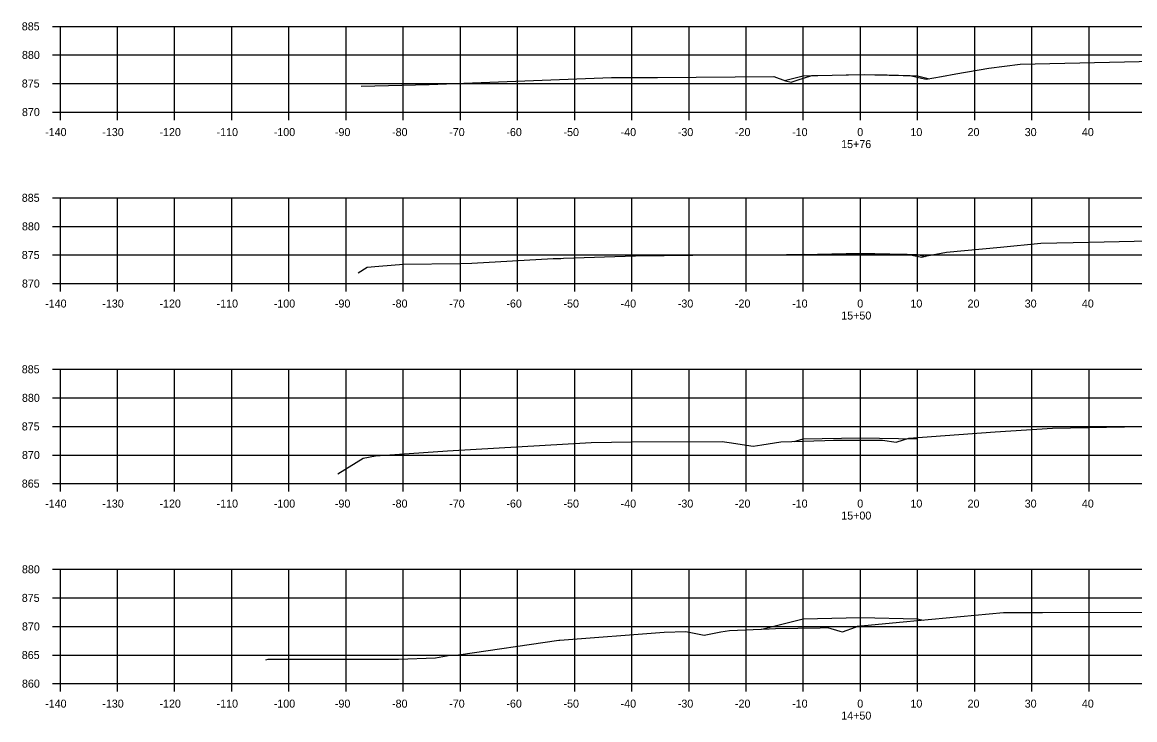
# Model space of a CAD drawing. Extents: x 1098669 to 1198896, y 698679 to 704410.
# Drawn here: x 1110634.5 to 1110829.2, y 701942.8 to 702064.8 of the extents above; entities that cross this region are included whole.
import ezdxf

# ---------------------------------------------------------------- set-up
doc = ezdxf.new("R2010")
doc.units = 0
for name, color, linetype in [('Proposed Surface', 7, 'Continuous'), ('R_Axis', 7, 'Continuous'), ('R_Axis Annot', 7, 'Continuous'), ('R_Fin Surface', 7, 'Continuous'), ('R_Grid', 7, 'Continuous')]:
    doc.layers.add(name, color=color, linetype=linetype)

msp = doc.modelspace()

# ---------------------------------------------------------------- linework, layer by layer
at = {"layer": 'Proposed Surface'}
for points in [[(1110693.81, 702053.64), (1110705.71, 702053.98), (1110737.59, 702055.16), (1110745.67, 702055.2), (1110766.01, 702055.35), (1110768.06, 702054.62), (1110769.01, 702054.38), (1110770.07, 702054.71), (1110772.65, 702055.53), (1110776.23, 702055.61), (1110781.94, 702055.71), (1110785.84, 702055.63), (1110789.87, 702055.55), (1110791.3, 702055.19), (1110792.68, 702054.87), (1110795.35, 702055.35), (1110797.85, 702055.84), (1110803.61, 702056.79), (1110809.13, 702057.49), (1110832.57, 702058.01)], [(1110693.25, 702021), (1110694.85, 702021.97), (1110696.91, 702022.15), (1110701.23, 702022.52), (1110711.07, 702022.64), (1110713.18, 702022.72), (1110727.38, 702023.5), (1110728.73, 702023.52), (1110729.17, 702023.55), (1110741.79, 702023.95), (1110751.8, 702024.08), (1110757.18, 702024.13), (1110765.02, 702024.17), (1110771.44, 702024.25), (1110772.09, 702024.24), (1110777.76, 702024.33), (1110781.26, 702024.39), (1110783.25, 702024.36), (1110789.31, 702024.28), (1110791.3, 702023.88), (1110791.9, 702023.77), (1110792.76, 702023.95), (1110796.24, 702024.62), (1110805.66, 702025.49), (1110812.7, 702026.2), (1110821.16, 702026.39), (1110849.97, 702027)], [(1110689.73, 701985.84), (1110694.15, 701988.56), (1110696.3, 701989.01), (1110708.92, 701989.85), (1110734.04, 701991.33), (1110741.15, 701991.42), (1110756.96, 701991.48), (1110758.17, 701991.31), (1110762.38, 701990.69), (1110763.88, 701990.93), (1110767.25, 701991.46), (1110774.91, 701991.67), (1110776.44, 701991.71), (1110777.03, 701991.72), (1110782.87, 701991.74), (1110784.96, 701991.75), (1110785.02, 701991.75), (1110787.4, 701991.37), (1110787.57, 701991.42), (1110789.64, 701992.1), (1110804.7, 701993.2), (1110814.79, 701993.81), (1110830.49, 701994.13)], [(1110677.13, 701953.27), (1110677.55, 701953.41), (1110700.33, 701953.42), (1110706.83, 701953.64), (1110709.36, 701954.08), (1110710.8, 701954.18), (1110728.38, 701956.71), (1110728.54, 701956.73), (1110746.83, 701958.16), (1110750.59, 701958.25), (1110752.95, 701957.77), (1110753.83, 701957.61), (1110756.75, 701958.17), (1110758.27, 701958.42), (1110765.17, 701958.73), (1110766.29, 701958.79), (1110774.11, 701958.91), (1110775.37, 701958.93), (1110777.54, 701958.31), (1110778.03, 701958.18), (1110780.32, 701959.03), (1110780.65, 701959.17), (1110788.65, 701959.92), (1110806.16, 701961.59), (1110812.99, 701961.56), (1110839.28, 701961.64)]]:
    msp.add_lwpolyline(points, dxfattribs=at)
at = {"layer": 'R_Axis'}
for p, q in [((1110639.76, 702064.13), (1110641.16, 702064.13)), ((1110641.16, 702049.13), (1110641.16, 702064.13)), ((1110639.76, 702059.13), (1110641.16, 702059.13)), ((1110639.76, 702054.13), (1110641.16, 702054.13)), ((1110639.76, 702049.13), (1110641.16, 702049.13)), ((1110641.16, 702049.13), (1110921.16, 702049.13)), ((1110641.16, 702047.73), (1110641.16, 702049.13)), ((1110651.16, 702047.73), (1110651.16, 702049.13)), ((1110661.16, 702047.73), (1110661.16, 702049.13)), ((1110671.16, 702047.73), (1110671.16, 702049.13)), ((1110681.16, 702047.73), (1110681.16, 702049.13)), ((1110691.16, 702047.73), (1110691.16, 702049.13)), ((1110701.16, 702047.73), (1110701.16, 702049.13)), ((1110711.16, 702047.73), (1110711.16, 702049.13)), ((1110721.16, 702047.73), (1110721.16, 702049.13)), ((1110731.16, 702047.73), (1110731.16, 702049.13)), ((1110741.16, 702047.73), (1110741.16, 702049.13)), ((1110751.16, 702047.73), (1110751.16, 702049.13)), ((1110761.16, 702047.73), (1110761.16, 702049.13)), ((1110771.16, 702047.73), (1110771.16, 702049.13)), ((1110781.16, 702047.73), (1110781.16, 702049.13)), ((1110791.16, 702047.73), (1110791.16, 702049.13)), ((1110801.16, 702047.73), (1110801.16, 702049.13)), ((1110811.16, 702047.73), (1110811.16, 702049.13)), ((1110821.16, 702047.73), (1110821.16, 702049.13)), ((1110639.76, 702034.13), (1110641.16, 702034.13)), ((1110641.16, 702019.13), (1110641.16, 702034.13)), ((1110639.76, 702029.13), (1110641.16, 702029.13)), ((1110639.76, 702024.13), (1110641.16, 702024.13)), ((1110639.76, 702019.13), (1110641.16, 702019.13)), ((1110641.16, 702019.13), (1110921.16, 702019.13)), ((1110641.16, 702017.73), (1110641.16, 702019.13)), ((1110651.16, 702017.73), (1110651.16, 702019.13)), ((1110661.16, 702017.73), (1110661.16, 702019.13)), ((1110671.16, 702017.73), (1110671.16, 702019.13)), ((1110681.16, 702017.73), (1110681.16, 702019.13)), ((1110691.16, 702017.73), (1110691.16, 702019.13)), ((1110701.16, 702017.73), (1110701.16, 702019.13)), ((1110711.16, 702017.73), (1110711.16, 702019.13)), ((1110721.16, 702017.73), (1110721.16, 702019.13)), ((1110731.16, 702017.73), (1110731.16, 702019.13)), ((1110741.16, 702017.73), (1110741.16, 702019.13)), ((1110751.16, 702017.73), (1110751.16, 702019.13)), ((1110761.16, 702017.73), (1110761.16, 702019.13)), ((1110771.16, 702017.73), (1110771.16, 702019.13)), ((1110781.16, 702017.73), (1110781.16, 702019.13)), ((1110791.16, 702017.73), (1110791.16, 702019.13)), ((1110801.16, 702017.73), (1110801.16, 702019.13)), ((1110811.16, 702017.73), (1110811.16, 702019.13)), ((1110821.16, 702017.73), (1110821.16, 702019.13)), ((1110639.76, 702004.13), (1110641.16, 702004.13)), ((1110641.16, 701984.13), (1110641.16, 702004.13)), ((1110639.76, 701999.13), (1110641.16, 701999.13)), ((1110639.76, 701994.13), (1110641.16, 701994.13)), ((1110639.76, 701989.13), (1110641.16, 701989.13)), ((1110639.76, 701984.13), (1110641.16, 701984.13)), ((1110641.16, 701984.13), (1110921.16, 701984.13)), ((1110641.16, 701982.73), (1110641.16, 701984.13)), ((1110651.16, 701982.73), (1110651.16, 701984.13)), ((1110661.16, 701982.73), (1110661.16, 701984.13)), ((1110671.16, 701982.73), (1110671.16, 701984.13)), ((1110681.16, 701982.73), (1110681.16, 701984.13)), ((1110691.16, 701982.73), (1110691.16, 701984.13)), ((1110701.16, 701982.73), (1110701.16, 701984.13)), ((1110711.16, 701982.73), (1110711.16, 701984.13)), ((1110721.16, 701982.73), (1110721.16, 701984.13)), ((1110731.16, 701982.73), (1110731.16, 701984.13)), ((1110741.16, 701982.73), (1110741.16, 701984.13)), ((1110751.16, 701982.73), (1110751.16, 701984.13)), ((1110761.16, 701982.73), (1110761.16, 701984.13)), ((1110771.16, 701982.73), (1110771.16, 701984.13)), ((1110781.16, 701982.73), (1110781.16, 701984.13)), ((1110791.16, 701982.73), (1110791.16, 701984.13)), ((1110801.16, 701982.73), (1110801.16, 701984.13)), ((1110811.16, 701982.73), (1110811.16, 701984.13)), ((1110821.16, 701982.73), (1110821.16, 701984.13)), ((1110639.76, 701969.13), (1110641.16, 701969.13)), ((1110641.16, 701949.13), (1110641.16, 701969.13)), ((1110639.76, 701964.13), (1110641.16, 701964.13)), ((1110639.76, 701959.13), (1110641.16, 701959.13)), ((1110639.76, 701954.13), (1110641.16, 701954.13)), ((1110639.76, 701949.13), (1110641.16, 701949.13)), ((1110641.16, 701949.13), (1110921.16, 701949.13)), ((1110641.16, 701947.73), (1110641.16, 701949.13)), ((1110651.16, 701947.73), (1110651.16, 701949.13)), ((1110661.16, 701947.73), (1110661.16, 701949.13)), ((1110671.16, 701947.73), (1110671.16, 701949.13)), ((1110681.16, 701947.73), (1110681.16, 701949.13)), ((1110691.16, 701947.73), (1110691.16, 701949.13)), ((1110701.16, 701947.73), (1110701.16, 701949.13)), ((1110711.16, 701947.73), (1110711.16, 701949.13)), ((1110721.16, 701947.73), (1110721.16, 701949.13)), ((1110731.16, 701947.73), (1110731.16, 701949.13)), ((1110741.16, 701947.73), (1110741.16, 701949.13)), ((1110751.16, 701947.73), (1110751.16, 701949.13)), ((1110761.16, 701947.73), (1110761.16, 701949.13)), ((1110771.16, 701947.73), (1110771.16, 701949.13)), ((1110781.16, 701947.73), (1110781.16, 701949.13)), ((1110791.16, 701947.73), (1110791.16, 701949.13)), ((1110801.16, 701947.73), (1110801.16, 701949.13)), ((1110811.16, 701947.73), (1110811.16, 701949.13)), ((1110821.16, 701947.73), (1110821.16, 701949.13))]:
    msp.add_line(p, q, dxfattribs=at)
at = {"layer": 'R_Fin Surface'}
for points in [[(1110767.89, 702054.68), (1110767.89, 702054.68), (1110771.16, 702055.49), (1110771.17, 702055.49), (1110781.16, 702055.69), (1110791.15, 702055.49), (1110791.16, 702055.49), (1110791.16, 702055.49), (1110793.24, 702054.97)], [(1110771.16, 702024.22), (1110781.16, 702024.42), (1110791.16, 702024.22), (1110792.48, 702023.89)], [(1110769.55, 701991.52), (1110771.16, 701991.93), (1110781.16, 701992.13), (1110791.16, 701991.93)], [(1110763.9, 701958.67), (1110771.16, 701960.49), (1110781.16, 701960.69), (1110791.16, 701960.49), (1110792.11, 701960.25)]]:
    msp.add_lwpolyline(points, dxfattribs=at)
at = {"layer": 'R_Grid'}
for p, q in [((1110641.16, 702064.13), (1110921.16, 702064.13)), ((1110641.16, 702049.13), (1110641.16, 702064.13)), ((1110651.16, 702049.13), (1110651.16, 702064.13)), ((1110661.16, 702049.13), (1110661.16, 702064.13)), ((1110671.16, 702049.13), (1110671.16, 702064.13)), ((1110681.16, 702049.13), (1110681.16, 702064.13)), ((1110691.16, 702049.13), (1110691.16, 702064.13)), ((1110701.16, 702049.13), (1110701.16, 702064.13)), ((1110711.16, 702049.13), (1110711.16, 702064.13)), ((1110721.16, 702049.13), (1110721.16, 702064.13)), ((1110731.16, 702049.13), (1110731.16, 702064.13)), ((1110741.16, 702049.13), (1110741.16, 702064.13)), ((1110751.16, 702049.13), (1110751.16, 702064.13)), ((1110761.16, 702049.13), (1110761.16, 702064.13)), ((1110771.16, 702049.13), (1110771.16, 702064.13)), ((1110781.16, 702049.13), (1110781.16, 702064.13)), ((1110791.16, 702049.13), (1110791.16, 702064.13)), ((1110801.16, 702049.13), (1110801.16, 702064.13)), ((1110811.16, 702049.13), (1110811.16, 702064.13)), ((1110821.16, 702049.13), (1110821.16, 702064.13)), ((1110641.16, 702059.13), (1110921.16, 702059.13)), ((1110641.16, 702054.13), (1110921.16, 702054.13)), ((1110641.16, 702049.13), (1110921.16, 702049.13)), ((1110641.16, 702034.13), (1110921.16, 702034.13)), ((1110641.16, 702019.13), (1110641.16, 702034.13)), ((1110651.16, 702019.13), (1110651.16, 702034.13)), ((1110661.16, 702019.13), (1110661.16, 702034.13)), ((1110671.16, 702019.13), (1110671.16, 702034.13)), ((1110681.16, 702019.13), (1110681.16, 702034.13)), ((1110691.16, 702019.13), (1110691.16, 702034.13)), ((1110701.16, 702019.13), (1110701.16, 702034.13)), ((1110711.16, 702019.13), (1110711.16, 702034.13)), ((1110721.16, 702019.13), (1110721.16, 702034.13)), ((1110731.16, 702019.13), (1110731.16, 702034.13)), ((1110741.16, 702019.13), (1110741.16, 702034.13)), ((1110751.16, 702019.13), (1110751.16, 702034.13)), ((1110761.16, 702019.13), (1110761.16, 702034.13)), ((1110771.16, 702019.13), (1110771.16, 702034.13)), ((1110781.16, 702019.13), (1110781.16, 702034.13)), ((1110791.16, 702019.13), (1110791.16, 702034.13)), ((1110801.16, 702019.13), (1110801.16, 702034.13)), ((1110811.16, 702019.13), (1110811.16, 702034.13)), ((1110821.16, 702019.13), (1110821.16, 702034.13)), ((1110641.16, 702029.13), (1110921.16, 702029.13)), ((1110641.16, 702024.13), (1110921.16, 702024.13)), ((1110641.16, 702019.13), (1110921.16, 702019.13)), ((1110641.16, 702004.13), (1110921.16, 702004.13)), ((1110641.16, 701984.13), (1110641.16, 702004.13)), ((1110651.16, 701984.13), (1110651.16, 702004.13)), ((1110661.16, 701984.13), (1110661.16, 702004.13)), ((1110671.16, 701984.13), (1110671.16, 702004.13)), ((1110681.16, 701984.13), (1110681.16, 702004.13)), ((1110691.16, 701984.13), (1110691.16, 702004.13)), ((1110701.16, 701984.13), (1110701.16, 702004.13)), ((1110711.16, 701984.13), (1110711.16, 702004.13)), ((1110721.16, 701984.13), (1110721.16, 702004.13)), ((1110731.16, 701984.13), (1110731.16, 702004.13)), ((1110741.16, 701984.13), (1110741.16, 702004.13)), ((1110751.16, 701984.13), (1110751.16, 702004.13)), ((1110761.16, 701984.13), (1110761.16, 702004.13)), ((1110771.16, 701984.13), (1110771.16, 702004.13)), ((1110781.16, 701984.13), (1110781.16, 702004.13)), ((1110791.16, 701984.13), (1110791.16, 702004.13)), ((1110801.16, 701984.13), (1110801.16, 702004.13)), ((1110811.16, 701984.13), (1110811.16, 702004.13)), ((1110821.16, 701984.13), (1110821.16, 702004.13)), ((1110641.16, 701999.13), (1110921.16, 701999.13)), ((1110641.16, 701994.13), (1110921.16, 701994.13)), ((1110641.16, 701989.13), (1110921.16, 701989.13)), ((1110641.16, 701984.13), (1110921.16, 701984.13)), ((1110641.16, 701969.13), (1110921.16, 701969.13)), ((1110641.16, 701949.13), (1110641.16, 701969.13)), ((1110651.16, 701949.13), (1110651.16, 701969.13)), ((1110661.16, 701949.13), (1110661.16, 701969.13)), ((1110671.16, 701949.13), (1110671.16, 701969.13)), ((1110681.16, 701949.13), (1110681.16, 701969.13)), ((1110691.16, 701949.13), (1110691.16, 701969.13)), ((1110701.16, 701949.13), (1110701.16, 701969.13)), ((1110711.16, 701949.13), (1110711.16, 701969.13)), ((1110721.16, 701949.13), (1110721.16, 701969.13)), ((1110731.16, 701949.13), (1110731.16, 701969.13)), ((1110741.16, 701949.13), (1110741.16, 701969.13)), ((1110751.16, 701949.13), (1110751.16, 701969.13)), ((1110761.16, 701949.13), (1110761.16, 701969.13)), ((1110771.16, 701949.13), (1110771.16, 701969.13)), ((1110781.16, 701949.13), (1110781.16, 701969.13)), ((1110791.16, 701949.13), (1110791.16, 701969.13)), ((1110801.16, 701949.13), (1110801.16, 701969.13)), ((1110811.16, 701949.13), (1110811.16, 701969.13)), ((1110821.16, 701949.13), (1110821.16, 701969.13)), ((1110641.16, 701964.13), (1110921.16, 701964.13)), ((1110641.16, 701959.13), (1110921.16, 701959.13)), ((1110641.16, 701954.13), (1110921.16, 701954.13)), ((1110641.16, 701949.13), (1110921.16, 701949.13))]:
    msp.add_line(p, q, dxfattribs=at)

# ---------------------------------------------------------------- texts
at = {"layer": 'R_Axis Annot'}
for s, p in [('885', (1110634.41, 702063.43)), ('880', (1110634.44, 702058.43)), ('875', (1110634.41, 702053.43)), ('870', (1110634.44, 702048.43)), ('-140', (1110638.5, 702044.93)), ('-130', (1110648.5, 702044.93)), ('-120', (1110658.5, 702044.93)), ('-110', (1110668.5, 702044.93)), ('-100', (1110678.5, 702044.93)), ('-90', (1110689.2, 702044.93)), ('-80', (1110699.2, 702044.93)), ('-70', (1110709.2, 702044.93)), ('-60', (1110719.2, 702044.93)), ('-50', (1110729.2, 702044.93)), ('-40', (1110739.2, 702044.93)), ('-30', (1110749.2, 702044.93)), ('-20', (1110759.2, 702044.93)), ('-10', (1110769.2, 702044.93)), ('0', (1110780.6, 702044.93)), ('10', (1110789.9, 702044.93)), ('20', (1110799.9, 702044.93)), ('30', (1110809.9, 702044.93)), ('40', (1110819.9, 702044.93)), ('15+76', (1110777.78, 702042.83)), ('885', (1110634.41, 702033.43)), ('880', (1110634.44, 702028.43)), ('875', (1110634.41, 702023.43)), ('870', (1110634.44, 702018.43)), ('-140', (1110638.5, 702014.93)), ('-130', (1110648.5, 702014.93)), ('-120', (1110658.5, 702014.93)), ('-110', (1110668.5, 702014.93)), ('-100', (1110678.5, 702014.93)), ('-90', (1110689.2, 702014.93)), ('-80', (1110699.2, 702014.93)), ('-70', (1110709.2, 702014.93)), ('-60', (1110719.2, 702014.93)), ('-50', (1110729.2, 702014.93)), ('-40', (1110739.2, 702014.93)), ('-30', (1110749.2, 702014.93)), ('-20', (1110759.2, 702014.93)), ('-10', (1110769.2, 702014.93)), ('0', (1110780.6, 702014.93)), ('10', (1110789.9, 702014.93)), ('20', (1110799.9, 702014.93)), ('30', (1110809.9, 702014.93)), ('40', (1110819.9, 702014.93)), ('15+50', (1110777.8, 702012.83)), ('885', (1110634.41, 702003.43)), ('880', (1110634.44, 701998.43)), ('875', (1110634.41, 701993.43)), ('870', (1110634.44, 701988.43)), ('865', (1110634.41, 701983.43)), ('-140', (1110638.5, 701979.93)), ('-130', (1110648.5, 701979.93)), ('-120', (1110658.5, 701979.93)), ('-110', (1110668.5, 701979.93)), ('-100', (1110678.5, 701979.93)), ('-90', (1110689.2, 701979.93)), ('-80', (1110699.2, 701979.93)), ('-70', (1110709.2, 701979.93)), ('-60', (1110719.2, 701979.93)), ('-50', (1110729.2, 701979.93)), ('-40', (1110739.2, 701979.93)), ('-30', (1110749.2, 701979.93)), ('-20', (1110759.2, 701979.93)), ('-10', (1110769.2, 701979.93)), ('0', (1110780.6, 701979.93)), ('10', (1110789.9, 701979.93)), ('20', (1110799.9, 701979.93)), ('30', (1110809.9, 701979.93)), ('40', (1110819.9, 701979.93)), ('15+00', (1110777.8, 701977.83)), ('880', (1110634.44, 701968.43)), ('875', (1110634.41, 701963.43)), ('870', (1110634.44, 701958.43)), ('865', (1110634.41, 701953.43)), ('860', (1110634.44, 701948.43)), ('-140', (1110638.5, 701944.93)), ('-130', (1110648.5, 701944.93)), ('-120', (1110658.5, 701944.93)), ('-110', (1110668.5, 701944.93)), ('-100', (1110678.5, 701944.93)), ('-90', (1110689.2, 701944.93)), ('-80', (1110699.2, 701944.93)), ('-70', (1110709.2, 701944.93)), ('-60', (1110719.2, 701944.93)), ('-50', (1110729.2, 701944.93)), ('-40', (1110739.2, 701944.93)), ('-30', (1110749.2, 701944.93)), ('-20', (1110759.2, 701944.93)), ('-10', (1110769.2, 701944.93)), ('0', (1110780.6, 701944.93)), ('10', (1110789.9, 701944.93)), ('20', (1110799.9, 701944.93)), ('30', (1110809.9, 701944.93)), ('40', (1110819.9, 701944.93)), ('14+50', (1110777.8, 701942.83))]:
    msp.add_text(s, height=1.4, dxfattribs=at).set_placement(p)

doc.saveas('drawing.dxf')
